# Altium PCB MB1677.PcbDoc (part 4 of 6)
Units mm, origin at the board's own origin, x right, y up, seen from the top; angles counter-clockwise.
Board outline 78 x 105 mm, 6 copper layers (Top Layer, Signal Layer 1, Signal Layer 2, Signal Layer 3, Signal Layer 4, Bottom Layer), stack 1.574 mm thick; 404 components, 325 nets, 1691 pads, 961 vias.
Unrouted connection lines stored in the file: 9.
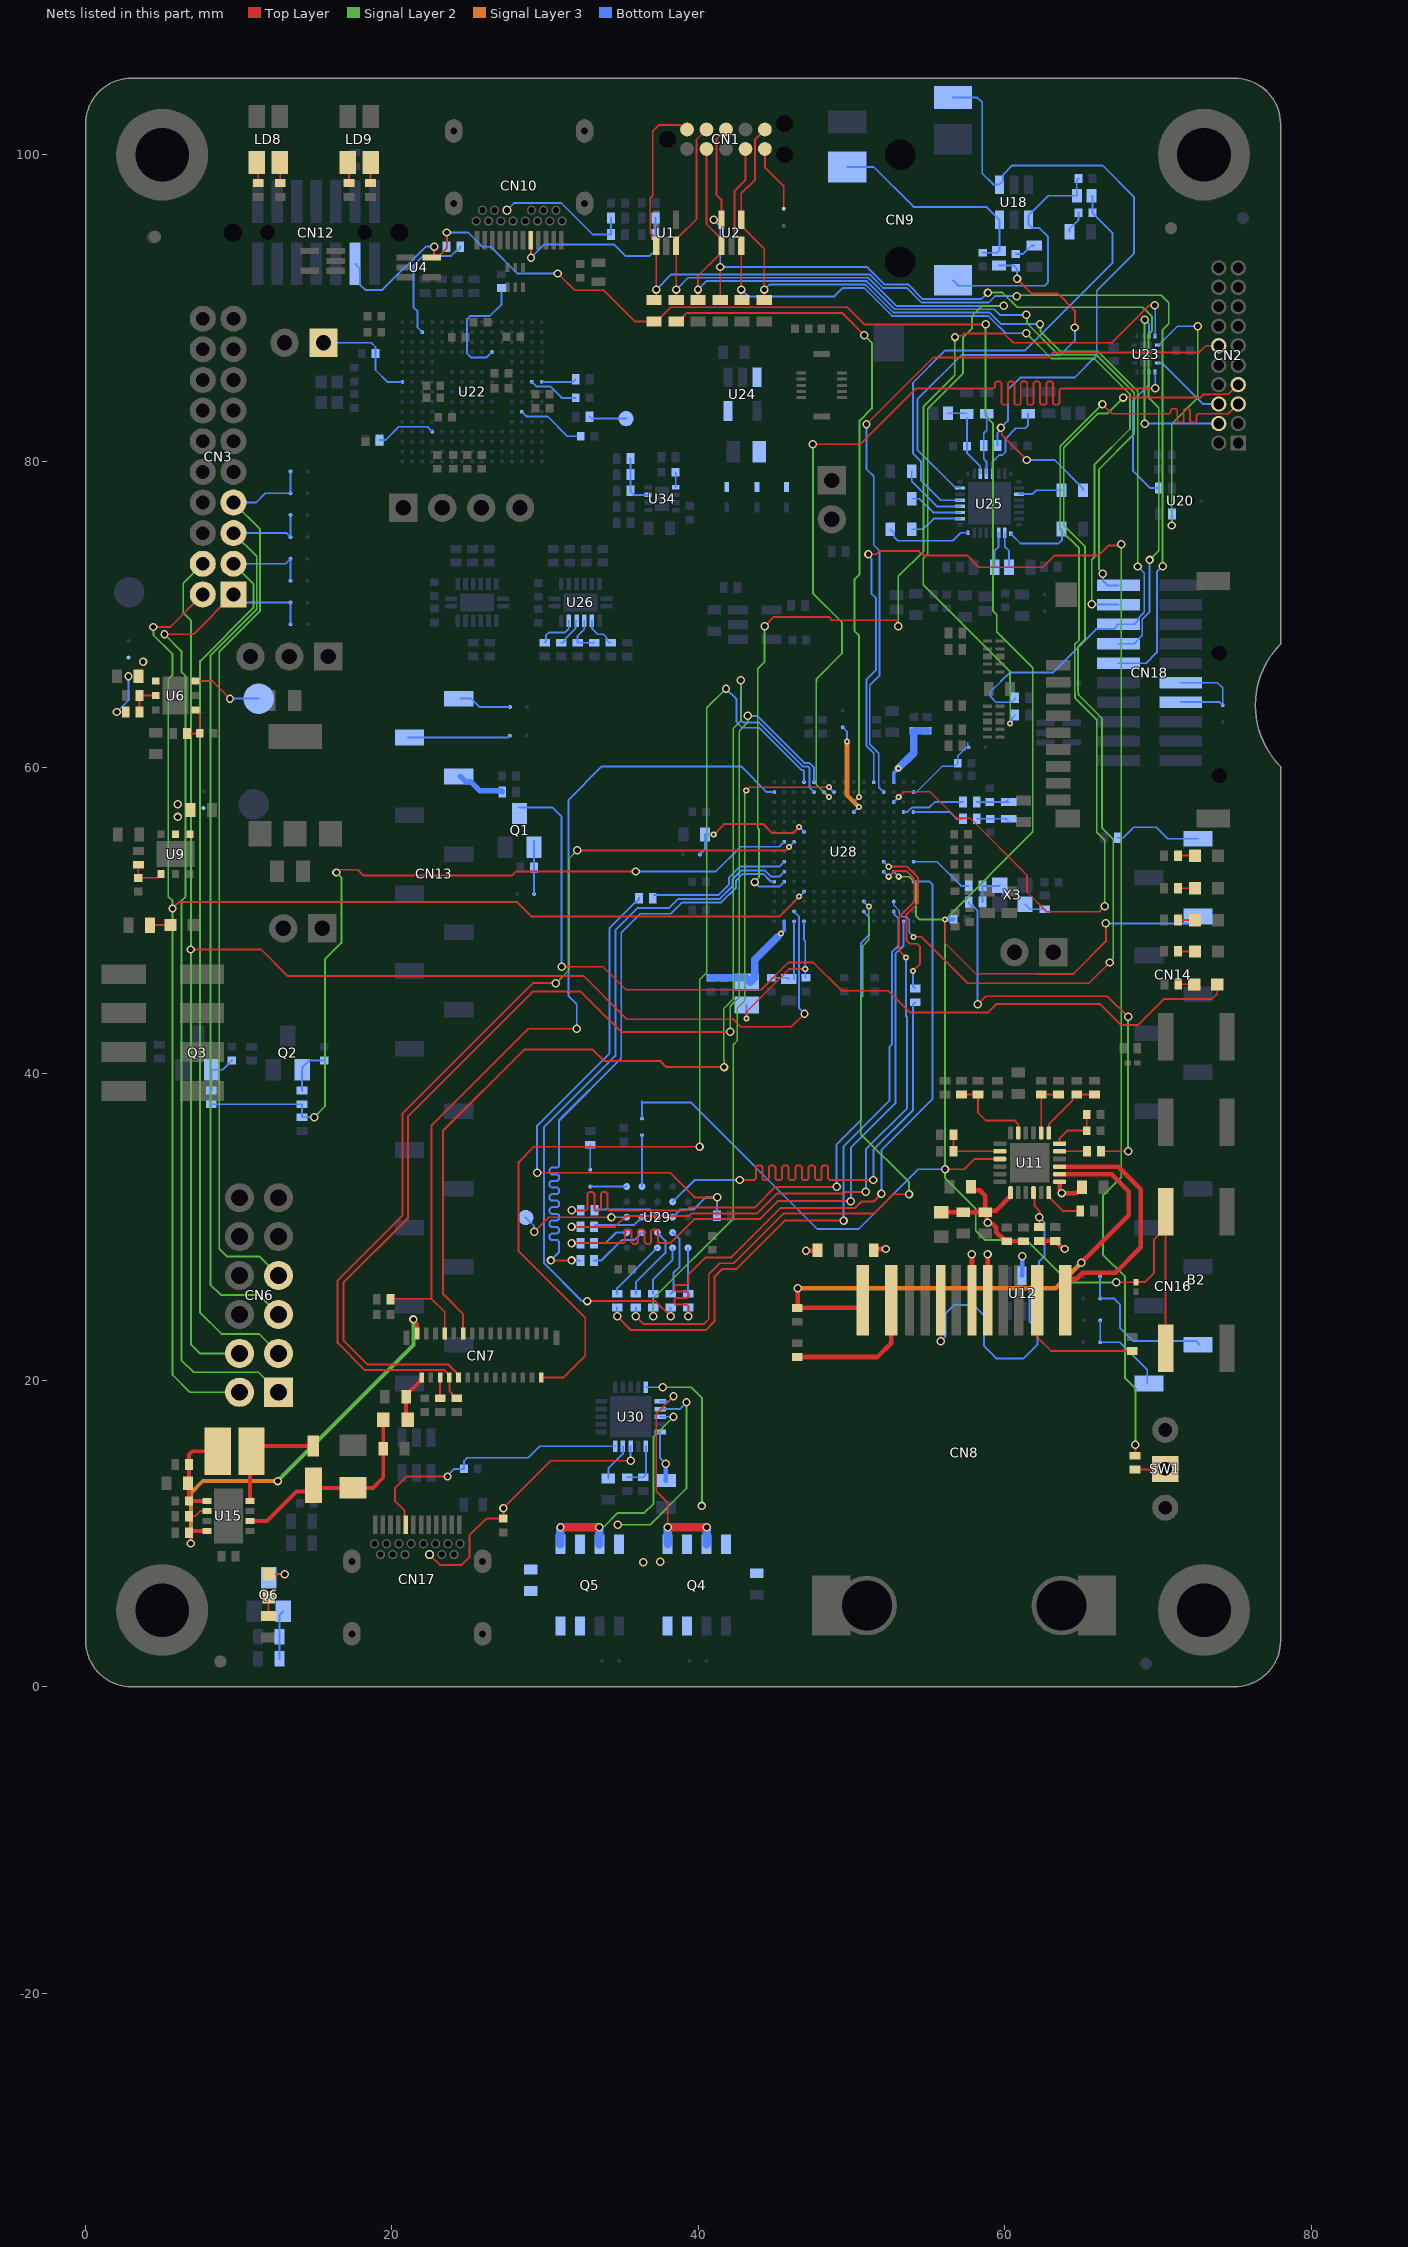
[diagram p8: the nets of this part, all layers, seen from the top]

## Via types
v1: diameter 0.55, hole 0.35, Top Layer to Bottom Layer, tented both sides, 748 vias
v2: diameter 0.4, hole 0.2, Top Layer to Bottom Layer, tented both sides, 203 vias
v3: diameter 0.6, hole 0.3, Top Layer to Bottom Layer, tented both sides, 9 vias
v4: diameter 0.55, hole 0.33, Top Layer to Bottom Layer, tented both sides, 1 vias

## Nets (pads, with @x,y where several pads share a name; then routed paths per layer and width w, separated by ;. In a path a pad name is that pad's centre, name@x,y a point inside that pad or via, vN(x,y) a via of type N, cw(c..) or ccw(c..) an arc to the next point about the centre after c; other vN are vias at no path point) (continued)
LCD_NE1_CS: CN7.22 R44.1 U28.G13 | length 63.8
  Top Layer w0.13: R44.1@24.225,18.825 24.13,18.825 23.94,19.015 23.94,19.11 23.74,19.31 CN7.22@23.74,20.175 23.74,20.35 23.617,20.474 23.425,20.665 18.235,20.665 16.45,22.45 16.45,26.525 20.68,30.755 20.68,37.41 29.025,45.755 29.195,45.925 v1(30.7,45.925) ; v1(32.1,54.6) 36.4,54.6 45.7,54.6 v2(45.925,54.825)
  Signal Layer 2 w0.1: v1(30.7,45.925) 31.525,46.75 31.525,54.025 v1(32.1,54.6)
  Bottom Layer w0.13: v2(45.925,54.825) U28.G13@46.25,55.15
LCD_NOE: CN7.19 U28.B11 | length 70.6
  Top Layer w0.13: CN7.19@24.64,23.05 24.64,24.328 23.33,25.638 23.33,36.294 28.621,41.585 30.148,41.585 33.103,41.585 33.843,40.845 37.504,40.845 37.899,40.45 v1(41.675,40.45)
  Signal Layer 2 w0.1: v1(41.675,40.45) 41.675,40.955 41.65,40.98 41.65,41.625 41.65,44.275 42.275,44.9 42.275,62.55 42.775,63.05 v1(42.775,65.7)
  Bottom Layer w0.13: v1(42.775,65.7) 42.775,63.075 42.925,62.925 43.959,62.925 46.747,60.137 46.814,60.07 47.139,60.07 47.25,59.959 47.25,58.7 U28.B11@47.55,58.4
LCD_NWE: CN7.20 U28.A11 | length 78.3
  Top Layer w0.13: CN7.20@24.34,20.175 24.255,20.26 24.255,20.445 23.655,21.045 18.392,21.045 16.83,22.607 16.83,26.367 21.06,30.597 21.06,37.253 29.182,45.375 32.325,45.375 33.562,44.137 34.955,42.745 36.4,42.745 42.07,42.745 v1(42.075,42.75)
  Signal Layer 2 w0.1: v1(42.075,42.75) 42.075,44.417 42.675,45.017 42.675,62.4 43.225,62.95 v1(43.225,63.375)
  Bottom Layer w0.13: v1(43.225,63.375) 43.834,63.375 46.909,60.3 47.25,60.3 47.55,60 U28.A11@47.55,59.05
LCD_PWR_ON: R101.1 R102.1 R103.2 U28.G14 | length 54.8
  Top Layer w0.12: v1(16.375,53.15) 16.55,53.325 17.775,53.325 18.15,52.95 27.825,52.95 28.09,53.215 v1(35.915,53.215)
  Signal Layer 2 w0.12: v1(14.925,37.175) 15.625,37.875 15.625,47.475 16.7,48.55 16.7,52.825 v1(16.375,53.15)
  Bottom Layer w0.12: R102.1@8.2,38.025 R101.1@14.125,38.025 R103.2@14.125,37.175 v1(14.925,37.175) ; v1@35.9,53.2 v1(35.915,53.215) 41.144,53.215 42.754,54.825 45.275,54.825 U28.G14@45.6,55.15
LCD_RST: CN7.23 R41.2 U28.B15 | length 58.8
  Top Layer w0.12: R41.2@19.953,25.325 22.575,25.325 ; CN7.23@23.44,23.05 23.44,24.46 22.575,25.325 ; v1(32.05,42.95) 28.9,42.95 22.575,36.625 22.575,25.325
  Bottom Layer w0.12: v1(32.05,42.95) 32.06,42.96 32.06,44.54 31.525,45.075 31.525,57.9 33.7,60.075 36.4,60.075 42.8,60.075 44.475,58.4 U28.B15@44.95,58.4
LCD_TE: CN7.2 U28.A12 | length 69.7
  Top Layer w0.12: CN7.2@29.74,20.175 31.191,20.175 32.62,21.605 32.62,24.08 28.265,28.435 28.265,34.25 29.265,35.25 v1(40.075,35.25)
  Signal Layer 2 w0.1: v1(40.075,35.25) 40.075,46.15 40.55,46.625 40.55,63.9 v1(41.8,65.15)
  Bottom Layer w0.12: v1(41.8,65.15) 42.49,64.46 42.49,62.96 42.848,62.602 43.964,62.602 46.721,59.845 46.83,59.845 46.9,59.775 U28.A12@46.9,59.05
LED_A: C49.2 CN7.28 L2.2 | length 3.3
  Top Layer w0.25: L2.2@21.025,17.425 20.925,17.525 20.925,19.05 21.85,19.975 21.915,19.975 21.94,20 CN7.28@21.94,20.175
LED_K: CN7.29 R52.2 U15.4 | length 26.5
  Top Layer w0.25: v1(6.875,9.35) 6.875,9.925 R52.2@6.75,10.05 6.875,10.175 U15.4@7.925,10.175 ; v1(21.4,23.975) 21.4,23.941 21.651,23.69 21.651,23.061 CN7.29@21.64,23.05
  Signal Layer 2 w0.25: v1@12.537,13.437 21.4,22.3 v1(21.4,23.975)
  Signal Layer 3 w0.25: v1(6.875,9.35) 6.875,12.657 7.643,13.425 v1(12.55,13.425)
MEMS_LED: CN2.12 U28.B4 | length 50.1
  Top Layer w0.12: v1(50.975,82.4) 55.339,86.764 62.814,86.764 63.15,87.1 72.7,87.1 73.135,87.535 CN2.12@73.965,87.535
  Bottom Layer w0.12: v1(50.975,82.4) 50.975,79.475 51.45,79 51.45,74.525 51.79,74.185 51.825,74.15 51.825,66.01 51.185,65.37 51.185,61.515 51.775,60.925 51.775,58.725 U28.B4@52.1,58.4
MICVDD: C69.2 C73.2 L5.2 U25.19 | length 5.2
  Bottom Layer w0.12: L5.2@56.3,83.125 C69.2@57.475,83.125 ; C69.2@57.525,82.825 C73.2@57.525,80.975 57.525,80.55 58.4,79.675 U25.19@58.4,79.175
NetC22_2: C22.2 R15.2 SB10.1 U6.4 | length 3.2
  Top Layer w0.12: v1(2.025,63.625) R15.2@2.625,63.625
  Bottom Layer w0.12: v1(2.025,63.625) 2.8,64.4 v1(2.8,65.95)
  other v1: 3.75,66.9
NetC26_2: C26.2 R17.2 U6.1 | length 2.5
  Top Layer w0.12: R17.2@6.625,62.225 C26.2@7.45,62.225 7.45,63.475 7.365,63.56 7.365,63.585 7.2,63.75 U6.1@7.175,63.75
NetC27_2: C27.2 SB13.1 U9.4 U9.5
  other v1: 6.025,56.775 6.025,57.6
NetC34_2: C34.2 R19.2 U9.1 | length 2.4
  Top Layer w0.1: R19.2@3.45,53.65 C34.2@3.45,52.8 4.675,52.8 4.725,52.85 4.75,52.85 4.925,53.025 U9.1@4.925,53.05
NetC38_2: C38.2 C39.2 U11.6 | length 3.4
  Top Layer w0.12: U11.6@63.575,35.45 63.575,35.8 64.075,36.3 C39.2@65.35,36.3 C38.2@65.35,37.35
NetC40_1: C40.1 C41.2 C42.2 C43.2 C45.2 C46.2 CN8.5 CN8.6 L1.1 R110.2 R111.2 R112.2 R113.2 U11.1 U11.19 U12.5 | length 24.6
  Top Layer w0.3: v1(47.025,28.45) 47.675,28.45 C45.2@47.775,28.35 ; C46.2@51.45,28.35 51.45,28.405 51.62,28.575 v1(52.225,28.575) ; L1.1@55.85,30.975 C42.2@57.3,30.975 C43.2@58.725,30.975 ; C40.1@57.8,32.625 57.8,32.569 57.97,32.399 58.376,32.399 58.725,32.05 C43.2@58.725,30.975 ; v1(57.855,28.225) 57.86,28.22 CN8.6@57.86,25.22 ; v1(58.875,28.225) 58.88,28.22 CN8.5@58.88,25.22 ; U11.19@60.375,32.25 60.375,31.975 60.325,31.975 59.426,31.076 58.826,31.076 C43.2@58.725,30.975 ; R112.2@61.225,29.075 R113.2@60.125,29.075 60.03,29.075 59.925,29.18 59.925,29.2 59.45,29.675 59.45,29.975 59.196,30.229 58.926,30.229 v1(58.878,30.276) 58.83,30.324 58.83,30.87 C43.2@58.725,30.975 ; R111.2@62.25,29.1 R110.2@63.3,29.1 63.395,29.1 63.5,28.995 63.5,28.9 63.777,28.623 63.877,28.623 v1(63.925,28.575) ; U11.1@63.575,32.95 63.575,32.375 v1(63.725,32.225) 64.675,32.225 64.755,32.305 64.88,32.305 65.05,32.475 C41.2@65.05,32.6
  Bottom Layer w0.3: U12.5@61.125,26.82 61.15,26.845 v1(61.15,28.1) v1@61.125,28.1
NetC51_2: C51.2 C52.2 D1.2 L2.1 U15.6 | length 13.8
  Top Layer w0.25: U15.6@10.725,10.825 11.85,10.825 13.761,12.736 14.486,12.736 14.875,13.125 15.025,12.975 C51.2@17.45,12.975 18.75,12.975 19.425,13.65 C52.2@19.425,15.525 L2.1@19.425,17.425
NetC53_2: C53.2 C54.1 L3.1 R49.2 U15.1 | length 6.2
  Top Layer w0.25: U15.1@7.925,12.125 C54.1@6.75,12.125 6.75,13.2 C53.2@6.675,13.275 6.75,13.35 R49.2@6.75,14.5 6.75,15.15 6.975,15.375 L3.1@8.625,15.375
NetC59_2: C59.2 U22.M10 | length 7.6
  Bottom Layer w0.12: U22.M10@26.525,87.125 26.175,86.775 25.15,86.775 24.9,87.025 24.9,89.275 25.1,89.475 26.375,89.475 27.15,90.25 C59.2@27.15,91.05
NetC68_2: C68.2 JP5.1 U22.J1 | length 7.1
  Bottom Layer w0.12: JP5.1@15.525,87.725 18.65,87.725 18.925,87.45 C68.2@18.925,87.025 18.925,85.95 19.7,85.175 U22.J1@20.675,85.175
NetC70_2: C70.2 U22.J14 | length 3.3
  Bottom Layer w0.12: U22.J14@29.125,85.175 29.425,84.875 30.325,84.875 31.075,84.125 C70.2@32,84.125
NetC76_1: C76.1 U25.8 | length 5.7
  Bottom Layer w0.12: C76.1@52.525,75.55 52.785,75.29 52.785,75.04 53.025,74.8 56.6,74.8 57.125,75.325 U25.8@57.6,75.325
NetC76_2: C76.2 U25.10 | length 3.4
  Bottom Layer w0.12: C76.2@53.925,75.55 54.65,75.55 55.35,76.25 U25.10@57.075,76.25
NetC77_2: C77.2 U22.F13 | length 4.3
  Bottom Layer w0.12: U22.F13@28.475,83.225 28.775,82.925 30.15,82.925 31.45,81.625 C77.2@32.075,81.625
NetC78_2: C78.2 U34.1 | length 1
  Bottom Layer w0.12: C78.2@38.5,79.275 38.525,79.25 U34.1@38.525,78.3
NetC79_1: C79.1 R76.1 U25.20 | length 4.1
  Bottom Layer w0.12: U25.20@58.8,79.175 58.8,79.975 58.625,80.15 R76.1@58.625,81.025 58.625,81.825 58.825,82.025 C79.1@58.825,83.1
NetC80_2: C80.2 D2.2 D3.2 D4.2 U24.3 U24.5
NetC81_2: C81.2 U25.11 | length 3.5
  Bottom Layer w0.12: C81.2@53.925,77.55 54.425,77.55 55.325,76.65 U25.11@57.075,76.65
NetC82_1: C82.1 U25.27 | length 2.9
  Bottom Layer w0.12: U25.27@60.925,77.85 61.8,77.85 62.05,78.1 C82.1@63.7,78.1
NetC82_2: C82.2 CN9.2 R76.2 U18.1 | length 47.8
  Top Layer w0.12: v1(59.75,82.175) 59.805,82.12 59.805,81.72 61.425,80.1 v1(61.425,80.075)
  Bottom Layer w0.12: CN9.2@56.625,103.75 56.641,103.734 58.205,103.734 58.525,103.414 58.525,98.775 59.24,98.06 59.64,98.06 U18.1@59.65,98.05 59.89,98.29 59.89,98.69 60.5,99.3 66.38,99.3 68.425,97.255 68.425,93.55 66,91.125 66,86.9 64.55,85.45 61,85.45 60.2,84.65 60.2,82.625 v1(59.75,82.175) 59.75,82.059 59.525,81.834 R76.2@59.525,81.025 ; v1(61.425,80.075) 63.25,80.075 65.1,78.225 C82.2@65.1,78.1
NetC83_2: C83.2 U25.12 | length 4.5
  Bottom Layer w0.12: C83.2@53.925,79.35 53.925,78.681 55.556,77.05 U25.12@57.075,77.05
NetC84_2: C84.2 U25.21 | length 5.4
  Bottom Layer w0.12: U25.21@59.2,79.175 59.2,79.95 59.65,80.4 59.85,80.4 60.05,80.6 60.05,81.475 60.725,82.15 61.325,82.15 61.525,82.35 C84.2@61.525,83.1
NetC86_1: C86.1 R77.2 | length 1.5
  Bottom Layer w0.12: R77.2@64.225,94.975 64.225,95.155 64.82,95.75 C86.1@64.82,96.225
NetC86_2: C86.2 L9.1 U25.13 | length 30.9
  Bottom Layer w0.12: U25.13@57.075,77.45 55.825,77.45 54.525,78.75 54.525,80 54,80.525 54,85.1 56.125,87.225 59.95,87.225 61.325,87.225 67.025,92.925 67.025,94.895 65.72,96.2 65.72,97.255 L9.1@65.65,97.325
NetC87_1: C87.1 R79.2 | length 1.4
  Bottom Layer w0.12: C87.1@60.725,93.525 61.195,93.525 61.745,94.075 R79.2@61.925,94.075
NetC87_2: C87.2 L10.1 U25.15 | length 27.5
  Top Layer w0.12: v1(60.8,91.9) 60.8,91.87 61.72,90.95 63.45,90.95 64.575,89.825 v1(64.575,88.725)
  Bottom Layer w0.12: U25.15@57.075,78.25 57.025,78.3 56.75,78.3 54.3,80.75 54.3,84.05 57.175,86.925 63.625,86.925 64.575,87.875 v1(64.575,88.725) ; L10.1@59.625,92.775 60.575,92.775 C87.2@60.725,92.625 60.8,92.55 v1(60.8,91.9)
NetC95_1: C95.1 C96.2 C115.2 C116.1 L4.1 U28.A3 U28.R14 | length 12.3
  Bottom Layer w0.25: 45.175,48.95 45.6,49.375 U28.R14@45.6,49.95 ; U28.A3@52.75,59.05 52.75,59.65 v2(53.05,59.95)
  Bottom Layer w0.5: C116.1@40.825,46.275 C115.2@41.7,46.275 43.1,46.275 43.375,46 43.675,46.3 43.675,47.45 45.175,48.95 ; v2(53.05,59.95) 54.05,60.95 C96.2@54.05,62.4 C95.1@54.925,62.4
  other v2: 45.388,49.163
NetC100_2: C100.2 SB12.2 U28.B1 | length 5.3
  Bottom Layer w0.1: U28.B1@54.05,58.4 54.057,58.407 54.232,58.407 55.9,60.075 56.725,60.075 C100.2@56.925,60.275 56.925,60.75 57.471,61.296 57.596,61.296 SB12.2@57.625,61.325 ; 57.575,61.61 57.575,61.461 57.596,61.44 SB12.2@57.596,61.337
NetC102_2: C102.2 R88.1 X2.2 | length 2.3
  Bottom Layer w0.1: R88.1@58.175,57.75 C102.2@59.025,57.75 X2.2@60.25,57.75 ; X2.2@60.1,57.8 X2.2@60.25,57.95
NetC104_2: C104.2 R89.1 X2.1 | length 2.3
  Bottom Layer w0.1: R89.1@58.175,56.65 C104.2@59.05,56.65 X2.1@60.15,56.65 ; X2.1@60,56.7 X2.1@60.25,56.45
NetC105_2: C105.2 SB14.2 U28.F12 | length 8.7
  Top Layer w0.13: v2(41,55.625) 41.675,56.3 44.25,56.3 44.825,55.725 46.175,55.725 v2(46.575,56.125)
  Bottom Layer w0.13: SB14.2@40.1,54.325 40.425,54.65 C105.2@40.425,55.625 v2(41,55.625) ; v2(46.575,56.125) U28.F12@46.9,55.8
NetC113_2: C113.2 L4.2 U28.R12 | length 10
  Top Layer w0.12: v2(43.15,43.625) 43.15,44.075 45.925,46.85 v2(46.975,46.85)
  Bottom Layer w0.12: v2(43.15,43.625) L4.2@43.15,44.5 ; U28.R12@46.9,49.95 46.9,48.725 46.975,48.65 v2(46.975,46.85) ; v2@46.925,46.825 46.975,46.775 46.975,46.325 C113.2@47.025,46.275
NetC114_2: C114.2 R96.1 U28.R13 | length 4.9
  Bottom Layer w0.12: C114.2@44.75,46.275 45.825,46.275 R96.1@45.9,46.2 ; U28.R13@46.25,49.95 46.25,46.225 R96.1@46.275,46.2
NetC117_1: C117.1 Q2.1 R101.2 | length 3.1
  Bottom Layer w0.12: R101.2@14.125,38.925 14.125,40.25 Q2.1@14.15,40.275 14.15,40.435 14.59,40.875 C117.1@15.575,40.875
NetC118_1: C118.1 Q3.1 R102.2 | length 2.9
  Bottom Layer w0.12: R102.2@8.2,38.925 8.225,38.95 Q3.1@8.225,40.275 8.95,40.275 9.33,40.655 9.33,40.68 9.525,40.875 C118.1@9.55,40.875
NetC120_2: C120.2 CN17.A5 U30.15 | length 18.5
  Top Layer w0.12: CN17.A5@20.9,10.585 20.825,10.66 20.825,11.475 20.2,12.1 20.2,12.975 20.95,13.725 v1(23.625,13.725)
  Bottom Layer w0.12: v1(23.625,13.725) 23.625,13.775 24.07,14.22 C120.2@24.7,14.22 24.7,14.725 24.925,14.95 28.9,14.95 29.65,15.7 U30.15@34.575,15.7
NetC121_1: C121.1 U30.14 | length 2.5
  Bottom Layer w0.12: C121.1@34.125,13.6 34.125,14.25 35.075,15.2 U30.14@35.075,15.7
NetC123_2: C123.2 CN17.B5 U30.13 | length 18.4
  Top Layer w0.12: CN17.B5@22.45,8.625 23.125,7.95 24.55,7.95 25.05,8.45 25.05,9.875 26.15,10.975 26.77,10.975 C123.2@27.255,10.975 ; C123.2@27.275,10.975 C123.2@27.255,10.975 ; v1(35.575,14.75) 30.375,14.75 v1(27.275,11.65) 27.275,10.995 C123.2@27.255,10.975
  Bottom Layer w0.12: v1(35.575,14.75) U30.13@35.575,15.7
NetC124_1: C124.1 Q5.2 Q5.4 U30.7 | length 13
  Signal Layer 2 w0.12: v1(34.725,10.575) 36.85,10.575 39.225,12.95 v1(39.225,18.575)
  Bottom Layer w0.12: U30.7@37.5,18.125 38.775,18.125 v1(39.225,18.575)
NetC124_2: C124.2 Q4.7 Q4.8 Q5.7 Q5.8 R121.2 U30.10 | length 3.3
  Bottom Layer w0.12: U30.10@37.5,16.625 37.5,14.925 v1(37.875,14.55)
  Bottom Layer w0.3: R121.2@37.875,13.45 v1(37.875,14.55)
  other v1: 36.4,8.125 37.5,8.15
NetC125_1: C125.1 Q4.2 Q4.4 U30.5 | length 11
  Signal Layer 2 w0.12: v1(37.675,19.55) 39.525,19.55 40.225,18.85 v1(40.225,11.8)
  Bottom Layer w0.12: U30.5@36.575,19.55 v1(37.675,19.55)
NetC128_2: C128.2 CN9.6 L9.2 U18.4 | length 16.5
  Bottom Layer w0.12: CN9.6@56.625,91.8 56.975,91.45 62.6,91.45 62.825,91.675 62.825,94.65 62.265,95.21 61.79,95.21 61.55,95.45 61.55,96.05 62.825,97.325 L9.2@64.7,97.325 64.7,98.33 C128.2@64.82,98.45
NetC129_2: C129.2 CN9.4 L10.2 U18.6 | length 14.5
  Bottom Layer w0.12: CN9.4@49.725,99.2 51.45,99.2 54.05,96.6 58.8,96.6 U18.6@59.65,95.75 59.65,93.75 L10.2@59.625,93.725 59.505,93.605 C129.2@58.55,93.605
NetCN1_2: CN1.2 CN18.2 R6.1 U2.1 | length 57.4
  Top Layer w0.12: R6.1@39.975,90.525 39.975,92.1 41.36,93.485 41.36,93.91 U2.1@41.5,94.05 41.36,94.19 41.36,94.64 40.53,95.47 CN1.2@40.53,100.38
  Signal Layer 2 w0.12: v1@61.425,89.575 v1(61.4,89.55) 61.45,89.5 61.45,89 63.5,86.95 65.975,86.95 68.45,84.475 68.45,81.775 66.15,79.475 66.15,72.935 66.4,72.685 v1(66.4,72.65)
  Bottom Layer w0.12: v1(39.975,91.2) 40.526,91.751 50.991,91.751 52.828,89.914 59.311,89.914 59.675,89.55 v1(61.4,89.55) ; v1(66.4,72.65) 66.4,72.2 66.71,71.89 CN18.2@67.415,71.89
NetCN1_4: CN1.4 CN18.4 R8.1 U2.3 | length 55.6
  Top Layer w0.12: R8.1@42.85,90.525 42.8,90.575 v1(42.8,91.2) U2.3@42.8,94.05 42.8,94.45 42.66,94.59 42.636,94.59 42.35,94.876 42.35,97.625 43.07,98.345 CN1.4@43.07,100.38
  Signal Layer 2 w0.12: v1(61.4,88.35) 63.05,86.7 65.85,86.7 68.175,84.375 68.175,82.1 65.85,79.775 65.85,73.74 65.675,73.565 v1(65.675,70.65)
  Bottom Layer w0.12: v1(42.8,91.2) 43.25,90.75 48.875,90.75 49.436,91.311 50.809,91.311 52.646,89.474 58.926,89.474 60.05,88.35 v1(61.4,88.35) ; v1(65.675,70.65) 67.385,70.65 CN18.4@67.415,70.62
NetCN1_5: CN1.5 SB17.2 | length 4.4
  Top Layer w0.12: CN1.5@44.34,100.38 44.34,99.185 45.575,97.95 SB17.2@45.575,96.475
NetCN1_6: CN1.6 CN18.6 R9.1 R97.2 U2.4 | length 69.2
  Top Layer w0.12: R9.1@44.3,90.525 44.3,93.875 42.965,95.21 42.94,95.21 42.8,95.35 U2.4@42.8,95.75 42.8,97.475 43.7,98.375 43.7,101.01 CN1.6@44.34,101.65
  Signal Layer 2 w0.12: v1(62.3,88.925) 62.339,88.886 62.339,88.461 63.625,87.175 66.075,87.175 68.675,84.575 v1(68.675,73.125)
  Bottom Layer w0.1: 59.75,65.625 59.05,64.925 59.05,64.65 59.45,64.25 60.47,64.25 60.675,64.455 R97.2@60.675,64.55
  Bottom Layer w0.12: v1(44.3,91.2) 44.631,91.531 50.9,91.531 52.737,89.694 59.018,89.694 59.761,88.95 62.275,88.95 v1(62.3,88.925) ; 59.75,65.625 60.325,66.2 63.125,66.2 65.965,69.04 67.105,69.04 CN18.6@67.415,69.35 68.44,69.35 68.75,69.66 68.75,69.79 69.1,70.14 69.1,72.7 v1(68.675,73.125)
NetCN1_8: CN1.8 CN18.8 R7.1 U2.5 | length 65.5
  Top Layer w0.12: v1(41,95.75) U2.5@41.5,95.75 41.5,97.075 41.175,97.4 41.175,101.025 CN1.8@41.8,101.65 ; R7.1@41.425,90.525 v1(41.425,92.675)
  Signal Layer 2 w0.12: v1(58.9,91) 59.85,91 60.8,90.05 69,90.05 69.6,89.45 69.6,88.475 69.39,88.265 69.39,84.93 69.39,84.135 70.05,83.475 70.05,74.15 v1(69.45,73.55)
  Bottom Layer w0.12: v1(41,95.75) 41.425,95.325 v1(41.425,92.675) 51,92.675 52.143,91.532 53.696,91.532 54.655,90.574 57.549,90.574 57.55,90.575 58.475,90.575 v1(58.9,91) ; CN18.8@67.415,68.08 68.44,68.08 68.75,68.39 68.75,68.4 68.975,68.625 68.975,69.683 69.45,70.158 v1(69.45,73.55)
NetCN1_9: CN1.9 R5.1 R98.2 U1.3 | length 67.7
  Top Layer w0.12: R5.1@38.55,90.525 U1.3@38.55,94.05 38.69,94.19 38.69,94.615 39.875,95.8 39.875,100.995 CN1.9@40.53,101.65
  Signal Layer 2 w0.1: v2(60.35,62.875) 60.35,65.625
  Signal Layer 2 w0.12: v1(59.932,90.134) 59.923,90.125 58.5,90.125 57.85,89.475 57.85,88.65 57.266,88.066 57.266,85.716 54.975,83.425 54.975,73.95 54.675,73.65 54.675,71.94 60.35,66.265 60.35,65.625
  Bottom Layer w0.1: v2(60.35,62.875) 60.47,62.995 60.47,63.22 R98.2@60.675,63.425
  Bottom Layer w0.12: v1(38.55,91.2) 39.321,91.971 51.082,91.971 52.919,90.134 v1(59.932,90.134) v1@59.932,90.135
NetCN1_10: CN1.10 CN18.10 R4.1 U1.1 | length 74.8
  Top Layer w0.12: R4.1@37.1,90.525 37.25,90.675 v1(37.25,91.2) U1.1@37.25,94.05 37.11,94.19 37.11,94.64 36.855,94.895 36.855,97.155 37.025,97.325 37.025,101.525 37.45,101.95 38.8,101.95 39.1,101.65 CN1.10@39.26,101.65
  Signal Layer 2 w0.12: v1(60.775,90.775) 60.825,90.825 70.2,90.825 70.697,90.328 70.697,88.972 70.3,88.575 v1(70.3,73.15)
  Bottom Layer w0.12: v1(37.25,91.2) 38.241,92.191 51.173,92.191 52.051,91.312 53.605,91.312 54.564,90.354 58.938,90.354 59.36,90.775 v1(60.775,90.775) ; CN18.10@67.415,66.81 69.22,66.81 69.925,67.515 69.925,72.775 v1(70.3,73.15)
NetCN7_24: CN7.24 R43.1 | length 1.4
  Top Layer w0.12: CN7.24@23.14,20.175 23.14,18.835 R43.1@23.15,18.825
NetCN8_1: CN8.1 U11.3 | length 16.7
  Top Layer w0.3: U11.3@63.575,33.95 67.4,33.95 68.875,32.475 68.875,28.675 67.225,27.025 65.075,27.025 64.689,26.639 64.305,26.639 63.96,26.294 CN8.1@63.96,25.22
NetCN8_2: CN8.2 R50.2 | length 9
  Top Layer w0.12: CN8.2@62.12,25.22 62.132,25.208 62.132,22.81 63.018,21.925 R50.2@68.325,21.925
NetCN8_11: CN8.11 R54.2 | length 9.3
  Top Layer w0.3: R54.2@46.47,21.505 R54.2@46.45,21.525 51.675,21.525 52.58,22.43 CN8.11@52.58,25.22
NetCN8_12: CN8.12 R53.2 U11.2 | length 36.1
  Top Layer w0.3: v1(46.475,26) 46.475,24.75 R53.2@46.45,24.725 50.485,24.725 50.74,24.98 CN8.12@50.74,25.22 ; U11.2@63.575,33.45 66.975,33.45 68.1,32.325 68.1,30.775 v1(64.995,27.67)
  Signal Layer 3 w0.3: v1(46.475,26) 63.325,26 v1(64.995,27.67)
NetCN10_A5: CN10.A5 R45.1 R46.1 | length 12.2
  Top Layer w0.12: CN10.A5@29.05,94.42 29.075,94.395 v1(29.075,93.275)
  Bottom Layer w0.12: v1(29.075,93.275) 29.95,94.15 34.475,94.15 35.225,93.4 36.825,93.4 37.2,93.775 R45.1@37.2,94.8 R46.1@37.2,95.875
NetCN10_B5: CN10.B5 R47.1 R48.1 | length 8.9
  Bottom Layer w0.12: CN10.B5@27.5,96.38 27.971,96.851 31.036,96.851 33.087,94.8 R48.1@34.3,94.8 R47.1@34.3,95.875
NetCN13_8: CN13.8 R95.1 | length 3.2
  Bottom Layer w0.35: CN13.8@24.466,59.419 24.801,59.084 25.133,59.084 25.724,58.492 27.12,58.492 27.2,58.412 R95.1@27.2,58.4
NetCN13_9: CN13.9 SB16.1 | length 6.7
  Bottom Layer w0.12: CN13.9@21.038,61.959 27.563,61.959 27.679,62.075 SB16.1@27.7,62.075
NetCN13_10: CN13.10 SB19.1 | length 3.5
  Bottom Layer w0.12: CN13.10@24.466,64.499 25.165,64.499 25.714,63.95 SB19.1@27.7,63.95
NetCN14_8: CN14.8 R90.1 | length 5.8
  Bottom Layer w0.12: R90.1@67.375,55.41 67.38,55.415 67.74,55.415 68.425,56.1 69.9,56.1 70.645,55.355 CN14.8@72.615,55.355
NetCN16_1: CN16.1 SB21.2 SB23.2 | length 6.1
  Bottom Layer w0.12: SB23.2@66.227,23.915 SB21.2@66.227,22.49 67.51,22.49 69.298,20.702 CN16.1@69.298,19.795
NetCN16_2: CN16.2 SB24.2 SB25.2 | length 10.1
  Bottom Layer w0.12: SB25.2@66.225,26.775 SB24.2@66.225,25.35 67.1,25.35 67.525,24.925 67.525,23.4 68.35,22.575 72.487,22.575 CN16.2@72.727,22.335
NetCN18_11: CN18.11 CN18.13 SB18.2 | length 6.8
  Bottom Layer w0.12: CN18.13@71.485,64.27 74.03,64.27 SB18.2@74.225,64.075 74.225,65.2 73.885,65.54 CN18.11@71.485,65.54
NetD1_1: D1.1 L3.2 U15.8 | length 7.5
  Top Layer w0.25: U15.8@10.725,12.125 10.725,15.275 L3.2@10.825,15.375 11.17,15.72 D1.1@14.875,15.72
NetLD1_2: LD1.2 R26.2 | length 1.1
  Top Layer w0.12: R26.2@71.3,48 72.405,48 LD1.2@72.415,47.99
NetLD2_2: LD2.2 R25.2 | length 1.1
  Top Layer w0.12: R25.2@71.3,50.05 72.405,50.05 LD2.2@72.415,50.04
NetLD3_2: LD3.2 R24.2 | length 1.1
  Top Layer w0.12: R24.2@71.3,52.125 72.405,52.125 LD3.2@72.415,52.115
NetLD4_2: LD4.2 R22.2 | length 1.1
  Top Layer w0.12: R22.2@71.3,54.25 72.405,54.25 LD4.2@72.415,54.24
NetLD5_1: LD5.1 R23.2 | length 1.3
  Top Layer w0.12: R23.2@4.21,49.713 4.223,49.725 LD5.1@5.547,49.725
NetLD6_1: LD6.1 R27.1 | length 1
  Top Layer w0.12: R27.1@71.328,45.85 72.355,45.85 LD6.1@72.365,45.84
NetLD6_2: LD6.2 Q1.3 | length 60.6
  Top Layer w0.12: v1(31.075,47) 33.775,47 35.275,45.5 44.1,45.5 45.875,47.275 47.5,47.275 49.35,45.425 52.4,45.425 53.825,44 58.9,44 59.475,44.575 66.2,44.575 67.575,43.2 68.7,43.2 70.4,44.9 73.525,44.9 73.865,45.24 LD6.2@73.865,45.84
  Bottom Layer w0.12: Q1.3@28.325,57.4 30.475,57.4 31.075,56.8 v1(31.075,47)
NetLD7_1: LD7.1 R56.1 | length 1.2
  Top Layer w0.12: R56.1@11.95,4.62 LD7.1@11.95,5.845
NetLD7_2: LD7.2 Q6.3 | length 2.2
  Top Layer w0.12: LD7.2@11.95,7.345 12.995,7.345 v1(13,7.35)
  Bottom Layer w0.12: Q6.3@11.95,7.12 12.18,7.35 v1(13,7.35)
NetLD8_1: LD8.1 R130.1 | length 1.4
  Top Layer w0.12: R130.1@12.709,98.15 12.709,99.474 LD8.1@12.735,99.5
NetLD8_2: LD8.2 R131.1 | length 1.4
  Top Layer w0.12: LD8.2@11.235,99.5 11.275,99.46 R131.1@11.275,98.15
NetLD9_1: LD9.1 R59.1 | length 1.4
  Top Layer w0.12: R59.1@18.6,98.15 18.6,99.49 LD9.1@18.61,99.5
NetLD9_2: LD9.2 R60.2 | length 1.4
  Top Layer w0.12: LD9.2@17.11,99.5 17.199,99.411 R60.2@17.199,98.15
NetQ1_1: Q1.1 R91.2 SB15.2 | length 3.5
  Bottom Layer w0.12: SB15.2@29.275,51.75 R91.2@29.275,53.45 Q1.1@29.275,55.2
NetQ4_1: Q4.1 Q4.3 U30.6 | length 15.1
  Top Layer w0.12: v1(38,10.4) 38,12 37.25,12.75 37.25,17.825 v1(38.375,18.95)
  Top Layer w0.55: v1(38,10.4) v1(40.54,10.4)
  Bottom Layer w0.12: U30.6@37.5,18.625 38.05,18.625 v1(38.375,18.95)
  Bottom Layer w0.3: v1@37.995,10.395 v1(38,10.4) ; v1@40.535,10.395 v1(40.54,10.4)
  Bottom Layer w0.55: Q4.1@37.995,9.305 v1@37.995,10.395 ; Q4.3@40.535,9.305 v1@40.535,10.395
NetQ5_1: Q5.1 Q5.3 U30.8 | length 16
  Top Layer w0.55: v1(31,10.4) v1(33.54,10.4)
  Signal Layer 2 w0.12: v1(33.54,10.4) 33.612,10.472 33.872,10.472 34.75,11.35 36.475,11.35 37.075,11.95 37.075,16.325 v1(38.375,17.625)
  Bottom Layer w0.12: U30.8@37.5,17.625 v1(38.375,17.625)
  Bottom Layer w0.3: v1@30.995,10.395 v1(31,10.4) ; v1@33.535,10.395 v1(33.54,10.4)
  Bottom Layer w0.55: Q5.1@30.995,9.305 v1@30.995,10.395 ; Q5.3@33.535,9.305 v1@33.535,10.395
NetQ6_1: Q6.1 R126.1 R127.2 | length 3.2
  Bottom Layer w0.12: R127.2@12.65,1.82 R126.1@12.65,3.27 12.65,4.67 Q6.1@12.9,4.92
NetR14_2: R14.2 R15.1 U6.5 | length 2.1
  Top Layer w0.12: R15.1@3.525,63.625 R14.2@3.525,64.7 U6.5@4.575,64.7
NetR28_2: R28.2 R35.1 U11.11 | length 5.8
  Top Layer w0.12: R35.1@57.175,38.65 R28.2@58.25,38.65 58.25,37.475 58.775,36.95 60.65,36.95 60.875,36.725 U11.11@60.875,36.15
NetR30_1: R30.1 R31.2 U11.8 | length 3.6
  Top Layer w0.12: U11.8@62.375,36.15 R30.1@62.375,38.65 R31.2@63.5,38.65
NetR32_1: R32.1 R33.2 U11.7 | length 4.4
  Top Layer w0.12: U11.7@62.875,36.15 62.875,36.725 64.44,38.29 64.44,38.455 64.635,38.65 R32.1@64.7,38.65 R33.2@65.85,38.65
NetR37_2: R37.2 R39.1 U11.14 | length 4.1
  Top Layer w0.12: R37.2@56.65,36.025 R39.1@56.65,34.95 U11.14@59.675,34.95
NetR38_1: R38.1 U11.5 | length 1.8
  Top Layer w0.12: U11.5@63.575,34.95 R38.1@65.375,34.95
NetR40_1: R40.1 U11.24 | length 2.7
  Top Layer w0.12: U11.24@62.875,32.25 62.875,31.983 62.964,31.894 62.981,31.894 63.825,31.05 R40.1@64.925,31.05
NetR42_1: R42.1 U28.A5 | length 94.1
  Top Layer w0.12: v1(51.1,73.925) 51.6,73.925 51.805,74.13 54.395,74.13 54.675,73.85 57.537,73.85 58.312,73.075 62.488,73.075 63.262,73.85 66.125,73.85 66.775,74.5 67.525,74.5 v1(67.6,74.575) ; R42.1@68.5,15.075 68.525,15.1 v1(68.525,15.8)
  Signal Layer 2 w0.12: v1(67.6,74.575) 67.6,33.25 66.4,32.05 66.4,28.2 67.85,26.75 67.85,20.15 68.525,19.475 v1(68.525,15.8)
  Bottom Layer w0.12: v1(51.1,73.925) 51.1,73.84 51.3,73.64 51.3,71.336 51.6,71.036 51.6,66.375 50.965,65.74 50.965,61.424 51.45,60.939 U28.A5@51.45,59.05
NetR42_2: R42.2 SW1.1 | length 2
  Top Layer w0.12: R42.2@68.5,14.175 70.425,14.175 SW1.1@70.475,14.225
NetR51_2: R51.2 U15.2 | length 1.3
  Top Layer w0.12: R51.2@6.75,11.125 7.15,11.125 7.5,11.475 U15.2@7.925,11.475
NetR57_2: R57.2 U25.1 | length 4.5
  Bottom Layer w0.12: U25.1@60.425,75.225 U25.1@60.4,75.25 60.4,75.21 60.45,75.16 60.49,75.16 61.025,74.625 63.525,74.625 63.725,74.825 R57.2@63.725,75.575
NetR61_1: R61.1 U26.14 | length 2.7
  Bottom Layer w0.12: R61.1@29.975,68.15 30.05,68.225 30.05,68.625 30.25,68.825 31.3,68.825 31.54,69.065 31.54,69.565 U26.14@31.55,69.575
NetR62_1: R62.1 U25.2 | length 2.4
  Bottom Layer w0.12: U25.2@60,75.325 60,74.425 60.275,74.15 R62.1@60.275,73.075
NetR63_1: R63.1 R72.1 U26.12 | length 2.7
  Bottom Layer w0.12: U26.12@32.55,69.575 32.55,69.04 32.115,68.605 32.115,68.16 R63.1@32.125,68.15 R72.1@33.2,68.15
NetR68_1: R68.1 U22.P3 | length 8.2
  Bottom Layer w0.12: U22.P3@21.975,88.425 21.675,88.725 21.675,89.775 21.4,90.05 21.4,92.75 22.05,93.4 23.85,93.4 24.16,93.71 24.255,93.71 24.45,93.905 R68.1@24.45,94
NetR69_1: R69.1 U26.13 | length 1.9
  Bottom Layer w0.12: R69.1@31.05,68.15 31.145,68.15 31.34,68.345 31.34,68.44 31.98,69.08 31.98,69.505 U26.13@32.05,69.575
NetR71_1: R71.1 U22.J15 | length 2.3
  Bottom Layer w0.12: U22.J15@29.775,85.175 31.825,85.175 R71.1@32,85.35
NetR73_1: R73.1 U25.3 | length 2.4
  Bottom Layer w0.12: R73.1@59.35,73.075 59.35,74.15 59.6,74.4 U25.3@59.6,75.325
NetR75_2: R75.2 TP13.1 | length 2.4
  Bottom Layer w0.12: R75.2@32.9,82.9 33.025,82.775 TP13.1@35.28,82.775
NetR78_1: R78.1 U26.11 | length 2.2
  Bottom Layer w0.12: U26.11@33.05,69.575 33.06,69.565 33.06,69.065 33.425,68.7 33.8,68.7 34.003,68.497 34.003,68.345 34.198,68.15 R78.1@34.275,68.15
NetR85_1: R85.1 U22.D4 | length 3.9
  Bottom Layer w0.12: R85.1@19.175,81.375 19.575,81.375 20.45,82.25 22.3,82.25 U22.D4@22.625,81.925
NetR86_1: R86.1 R128.1 R129.1 U34.7 | length 3.4
  Bottom Layer w0.12: R129.1@35.575,80.175 R86.1@35.575,79.125 R128.1@35.575,78.075 35.575,77.995 35.77,77.8 U34.7@36.725,77.8
NetR92_1: R92.1 R94.2 X3.3 | length 2.2
  Bottom Layer w0.12: R94.2@58.55,51.225 R92.1@58.55,52.275 59.625,52.275 X3.3@59.675,52.325
NetR92_2: R92.2 U28.J1 | length 4.3
  Bottom Layer w0.12: U28.J1@54.05,53.85 55.575,53.85 57.15,52.275 R92.2@57.65,52.275
NetR93_2: R93.2 X3.1 | length 1.4
  Bottom Layer w0.1: X3.1@61.325,51.075 61.65,50.75 62.125,50.75
  Bottom Layer w0.12: 62.125,50.75 R93.2@62.6,50.75
NetR104_1: R104.1 SB22.2 | length 1.6
  Bottom Layer w0.12: SB22.2@32.945,33.75 R104.1@32.945,35.375
NetR105_2: R105.2 U28.J4 | length 11.1
  Top Layer w0.12: 54.175,51 53.575,50.4 53.575,48.725 53.8,48.5 54.287,48.5 54.475,48.312
  Top Layer w0.13: v2(52.425,53.525) 53.625,53.525 54.32,52.83 54.32,51.145 54.175,51 ; v2(54,46.725) 54.475,47.2 54.475,48.312
  Bottom Layer w0.13: U28.J4@52.1,53.85 v2(52.425,53.525) ; v2(54,46.725) 54,45.725 R105.2@54.15,45.575
NetR106_1: R106.1 U28.J14 | length 9.7
  Bottom Layer w0.13: R106.1@37.1,51.665 41.303,51.665 41.995,52.357 41.995,52.814 42.706,53.525 45.275,53.525 U28.J14@45.6,53.85
NetR107_2: R107.2 U28.P6 | length 41.8
  Top Layer w0.13: v1(31.745,31.1) 32.67,31.1 32.778,31.207 32.778,32.181 32.885,32.289 33.1,32.289 33.208,32.181 33.208,31.185 33.315,31.077 33.53,31.077 33.638,31.185 33.638,32.181 33.745,32.289 33.96,32.289 34.068,32.181 34.068,31.207 34.175,31.1 34.741,31.1 39.228,31.1 39.408,31.28 43.68,31.28 45.025,32.625 v1(49.025,32.625)
  Bottom Layer w0.13: v1(31.745,31.1) R107.2@32.32,31.1 ; v1(49.025,32.625) 49.025,35.4 50.63,37.005 50.63,41.625 50.63,48.555 51.125,49.05 51.125,50.275 U28.P6@50.8,50.6
NetR109_1: R109.1 U28.K4 | length 45.4
  Top Layer w0.13: v1(31.72,30.025) 34.55,30.025 35.245,30.72 39.385,30.72 39.565,30.9 43.837,30.9 45.122,32.185 49.51,32.185 49.625,32.3 v1(50.925,32.3) ; v2(52.425,52.875) 52.8,53.25 53.575,53.25 54.09,52.735 54.09,51.24 53.1,50.25 53.1,48.05 v2(53.55,47.6)
  Bottom Layer w0.13: v1(31.72,30.025) R109.1@32.295,30.025 ; v1(50.925,32.3) 50.925,35.075 53.62,37.77 53.62,41.625 53.62,43.705 53.55,43.775 v2(53.55,47.6) ; U28.K4@52.1,53.2 v2(52.425,52.875)
NetR114_1: R114.1 U28.R2 | length 44.5
  Top Layer w0.13: v1(31.72,28.95) 35.027,28.95 35.092,28.95 35.199,29.057 35.199,29.752 35.307,29.859 35.522,29.859 35.629,29.752 35.629,29.019 35.737,28.911 35.952,28.911 36.059,29.019 36.059,29.752 36.167,29.859 36.382,29.859 36.489,29.752 36.489,29.019 36.597,28.911 36.812,28.911 36.919,29.019 36.919,29.752 37.027,29.859 37.242,29.859 37.349,29.752 37.349,29.057 37.457,28.95 37.775,28.95 38.152,28.95 39.722,30.52 43.995,30.52 45.175,31.7 v1(49.95,31.7)
  Bottom Layer w0.13: v1(31.72,28.95) R114.1@32.295,28.95 ; v1(49.95,31.7) 49.95,35.175 52.86,38.085 52.86,41.625 52.86,47.844 53.4,48.384 U28.R2@53.4,49.95
NetR115_1: R115.1 U28.L15 | length 43
  Top Layer w0.13: v1(30.375,27.825) v1(31.72,27.825)
  Bottom Layer w0.13: v1(30.375,27.825) 30.9,28.35 30.9,28.978 30.9,29.043 30.793,29.15 30.402,29.15 30.295,29.258 30.295,29.473 30.402,29.58 30.793,29.58 30.9,29.688 30.9,29.903 30.793,30.01 30.402,30.01 30.295,30.118 30.295,30.333 30.402,30.44 30.793,30.44 30.9,30.548 30.9,30.763 30.793,30.87 30.402,30.87 30.295,30.978 30.295,31.193 30.402,31.3 30.793,31.3 30.9,31.408 30.9,31.623 30.793,31.73 30.402,31.73 30.295,31.838 30.295,32.053 30.402,32.16 30.793,32.16 30.9,32.268 30.9,32.483 30.793,32.59 30.402,32.59 30.295,32.698 30.295,32.913 30.402,33.02 30.793,33.02 30.9,33.128 30.9,33.343 30.793,33.45 30.402,33.45 30.295,33.558 30.295,33.773 30.402,33.88 30.793,33.88 30.9,33.988 30.9,34.317 30.9,36.962 34.965,41.027 34.965,49.227 36.194,50.456 36.4,50.456 38.206,50.456 38.955,51.205 41.494,51.205 42.455,52.166 42.455,52.624 42.876,53.045 44.255,53.045 44.741,52.559 44.941,52.559 U28.L15@44.95,52.55 ; v1(31.72,27.825) R115.1@32.295,27.825
NetR116_1: R116.1 U28.L1 | length 44.1
  Top Layer w0.13: v1(39.345,24.175) 39.345,24.773 39.345,24.838 39.238,24.945 38.534,24.945 38.426,25.053 38.426,25.268 38.534,25.375 39.238,25.375 39.345,25.483 39.345,25.698 39.238,25.805 38.534,25.805 38.426,25.913 38.426,26.128 38.534,26.235 39.238,26.235 39.345,26.343 39.345,26.895 40.475,28.025 42.15,28.025 45.385,31.26 50.238,31.26 50.653,31.675 51.45,31.675 v1(51.95,32.175)
  Bottom Layer w0.13: v1(39.345,24.175) R116.1@39.345,24.75 ; v1(51.95,32.175) 51.95,35.025 55.275,38.35 55.275,41.625 55.275,52.375 55.1,52.55 U28.L1@54.05,52.55
NetR117_1: R117.1 U28.B9 | length 43.4
  Top Layer w0.1: v2(43.125,58.5) 43.35,58.725 v2(48.525,58.725)
  Signal Layer 2 w0.1: v1(37.045,24.175) 37.045,25.32 42.275,30.55 42.275,41.9 42.55,42.175 42.55,44.325 43.025,44.8 43.025,58.319 43.125,58.419 v2(43.125,58.5)
  Bottom Layer w0.13: v1(37.045,24.175) R117.1@37.045,24.75 ; v2(48.525,58.725) U28.B9@48.85,58.4
NetR118_2: R118.2 U28.N6 | length 44.6
  Top Layer w0.12: v1(35.92,24.175) 36.42,23.675 40.345,23.675 40.675,24.005 40.675,26.929 41.386,27.64 42.295,27.64 45.54,30.885 51.46,30.885 52.725,32.15 v1(53.75,32.15)
  Signal Layer 2 w0.12: v2(51.125,50.925) 51.125,48.75 50.725,48.35 50.725,45.1 50.6,44.975 50.6,36.075 53.75,32.925 v1(53.75,32.15)
  Bottom Layer w0.13: v1(35.92,24.175) R118.2@35.92,24.75 ; U28.N6@50.8,51.25 v2(51.125,50.925)
NetR119_1: R119.1 U28.K14 | length 47.1
  Top Layer w0.13: v1(32.75,25.175) 37.195,25.175 v1(38.195,24.175)
  Bottom Layer w0.13: v1(32.75,25.175) 32.403,25.175 29.915,27.663 29.915,36.515 34.585,41.185 34.585,49.385 36.036,50.836 36.4,50.836 38.086,50.836 38.685,51.435 41.399,51.435 42.225,52.261 42.225,52.45 42.225,52.719 42.781,53.275 44.35,53.275 44.725,52.9 44.95,52.9 45.3,52.9 U28.K14@45.6,53.2 ; v1(38.195,24.175) R119.1@38.195,24.75
NetR120_1: R120.1 U28.P3 | length 42.2
  Top Layer w0.13: v1(34.695,24.175) 35.57,23.3 40.5,23.3 41.05,23.85 41.05,26.773 41.542,27.265 42.465,27.265 45.626,30.426 45.628,30.425 v1(49.475,30.425)
  Bottom Layer w0.13: v1(34.695,24.175) R120.1@34.695,24.75 ; v1(49.475,30.425) 49.475,35.275 52.48,38.28 52.48,41.782 52.625,41.927 52.63,41.927 52.63,47.94 53.075,48.385 53.075,50.125 52.771,50.429 52.771,50.579 U28.P3@52.75,50.6
NetR122_2: R122.2 R123.1 U30.11 | length 3.1
  Bottom Layer w0.12: R123.1@35.35,13.675 R122.2@36.4,13.675 36.575,13.85 U30.11@36.575,15.7
NetSB11_2: SB11.2 U28.D7 | length 6.1
  Signal Layer 3 w0.3: v2(49.7,61.7) 49.7,58.2 v2(50.475,57.425)
  Bottom Layer w0.12: SB11.2@49.425,62.625 49.7,62.35 v2(49.7,61.7)
  Bottom Layer w0.13: U28.D7@50.15,57.1 v2(50.475,57.425)
NetSB20_2: SB20.2 U29.A4 | length 3.4
  Bottom Layer w0.13: U29.A4@36.32,32.65 SB20.2@36.32,36
NetSB22_1: SB22.1 U29.A5 | length 2.4
  Bottom Layer w0.13: SB22.1@32.945,32.65 U29.A5@35.32,32.65
NetTP3_1: TP3.1 U6.3 | length 4.6
  Top Layer w0.12: U6.3@7.175,65.65 8.275,65.65 v1(9.425,64.5)
  Bottom Layer w0.12: v1(9.425,64.5) TP3.1@11.3,64.5
NetTP5_1: TP5.1 U29.C5 | length 7.6
  Top Layer w0.12: v1(29.275,29.705) 30.225,30.655 30.23,30.65 v1(34.325,30.65)
  Bottom Layer w0.12: TP5.1@28.725,30.625 29.275,30.075 v1(29.275,29.705) v1@29.275,29.7 ; v1(34.325,30.65) U29.C5@35.32,30.65
NJTRST: R5.2 U28.C7 | length 44.5
  Top Layer w0.13: R5.2@38.55,89.125 38.73,89.125 38.985,89.38 38.985,89.41 39.25,89.675 49.375,89.675 v1(50.825,88.225)
  Signal Layer 2 w0.13: v2(50.475,58.075) 50.475,68.625 50.2,68.9 50.2,72.3 50.525,72.625 50.525,82.65 51.325,83.45 51.325,84.025 51.325,87.725 v1(50.825,88.225)
  Bottom Layer w0.13: U28.C7@50.15,57.75 v2(50.475,58.075)
NRST: B2.3 B2.4 C109.2 CN12.12 CN14.6 R4.2 R68.2 SB20.1 U4.5 U11.15 U14.1 U28.K3 | length 197.5
  Top Layer w0.1: v2(56.1,50.075) 56.1,48.55 58.125,46.525 62.125,46.525
  Top Layer w0.12: v1(22.75,94) 22.75,93.325 22.725,93.3 23,93.3 23.14,93.44 23.14,93.465 23.575,93.9 v1(23.575,94.925) ; v1(30.825,92.25) 31.925,91.15 33.829,91.15 34.316,90.663 35.854,89.125 R4.2@37.1,89.125 37.28,89.125 37.54,89.385 37.54,89.39 38.195,90.045 49.705,90.045 50.825,88.925 v1(58.75,88.925) ; v1(56.1,33.775) 57.35,33.775 58.025,34.45 U11.15@59.675,34.45 ; 62.125,46.525 64.475,46.525 66.6,48.65 v1(66.6,49.825) ; v1(67.275,26.4) 68.537,26.4 68.562,26.425 U14.1@68.575,26.412 69.137,26.412 69.75,27.025 69.75,29.2 70.06,29.51 70.06,30.56 B2.3@70.5,31 B2.4@70.5,22.1
  Signal Layer 2 w0.12: v2(53.075,52.875) 53.763,52.875 54.2,52.438 54.2,50.325 54.45,50.075 v2(56.1,50.075) ; v1(58.75,88.925) 58.75,82.95 59.225,82.475 59.225,70.225 59.475,69.975 59.475,68.85 61.825,66.5 61.825,55.8 v2(56.1,50.075) ; v1(67.275,26.4) 67.269,26.394 64.181,26.394 61.425,29.15 58.725,29.15 58.1,29.775 58.1,31.2 56.1,33.2 v1(56.1,33.775) v2(56.1,50.075)
  Bottom Layer w0.12: CN12.12@17.59,92.886 17.9,92.576 17.9,91.525 18.25,91.175 19.375,91.175 22.2,94 v1(22.75,94) ; R68.2@23.55,94 23.575,94.025 v1(23.575,94.925) 24.964,94.925 25.894,93.995 26.441,93.995 28.186,92.25 v1(30.825,92.25) ; SB20.1@36.32,37.1 36.32,38.195 36.325,38.19 36.325,38.125 39.525,38.125 47.775,29.875 50.45,29.875 54.35,33.775 v1(56.1,33.775) ; v1(66.6,49.825) 72.277,49.825 CN14.6@72.727,50.275
  Bottom Layer w0.13: U28.K3@52.75,53.2 v2(53.075,52.875)
  Bottom Layer w0.25: v2(56.1,50.075) 56.625,50.075 C109.2@56.65,50.1
OCS_25M: R38.2 R94.1 | length 28.4
  Top Layer w0.12: v1(58.225,44.55) 58.75,45.075 62.125,45.075 66.7,45.075 v1(68.05,43.725) ; R38.2@66.275,34.95 v1@68.2,34.95 ; v1(68.05,34.95) v1@68.2,34.95
  Signal Layer 2 w0.12: v1(68.05,34.95) v1(68.05,43.725)
  Bottom Layer w0.12: R94.1@57.65,51.225 57.65,51.13 57.845,50.935 57.94,50.935 58.225,50.65 v1(58.225,44.55)
OCSPI1_CLK: R105.1 U29.B2 | length 36.5
  Top Layer w0.13: v1(42.7,33.075) 43.572,33.075 43.638,33.075 43.745,33.182 43.745,33.919 43.853,34.027 44.068,34.027 44.175,33.919 44.175,33.169 44.283,33.062 44.498,33.062 44.605,33.169 44.605,33.919 44.713,34.027 44.928,34.027 45.035,33.919 45.035,33.169 45.143,33.062 45.358,33.062 45.465,33.169 45.465,33.919 45.573,34.027 45.788,34.027 45.895,33.919 45.895,33.169 46.003,33.062 46.218,33.062 46.325,33.169 46.325,33.919 46.433,34.027 46.648,34.027 46.755,33.919 46.755,33.169 46.863,33.062 47.078,33.062 47.185,33.169 47.185,33.919 47.293,34.027 47.508,34.027 47.615,33.919 47.615,33.169 47.723,33.062 47.938,33.062 48.045,33.169 48.045,33.919 48.152,34.027 48.368,34.027 48.475,33.919 48.475,33.182 48.582,33.075 49.123,33.075 v1(51.425,33.075)
  Bottom Layer w0.13: U29.B2@38.32,31.65 39.745,33.075 v1(42.7,33.075) ; v1(51.425,33.075) 51.425,35.037 54,37.612 54,44.525 R105.1@54.15,44.675
OCSPI1_DQS: R107.1 U29.C3 | length 4.3
  Bottom Layer w0.13: R107.1@33.22,31.1 33.27,31.15 36.82,31.15 U29.C3@37.32,30.65
OCSPI1_IO0: R118.1 U29.D3 | length 5
  Bottom Layer w0.13: R118.1@35.92,25.65 35.92,26.395 37.85,28.325 37.85,29.12 U29.D3@37.32,29.65
OCSPI1_IO1: R119.2 U29.D2 | length 4.4
  Bottom Layer w0.13: R119.2@38.195,25.65 38.375,25.83 38.375,27.025 38.775,27.425 38.775,29.195 U29.D2@38.32,29.65
OCSPI1_IO2: R109.2 U29.C4 | length 3.4
  Bottom Layer w0.13: R109.2@33.195,30.025 33.295,30.125 35.795,30.125 U29.C4@36.32,30.65
OCSPI1_IO3: R115.2 U29.D4 | length 3.9
  Bottom Layer w0.13: R115.2@33.195,27.825 33.675,27.825 35,29.15 35.82,29.15 U29.D4@36.32,29.65
OCSPI1_IO4: R114.2 U29.D5 | length 2.4
  Bottom Layer w0.13: R114.2@33.195,28.95 33.925,28.95 34.625,29.65 U29.D5@35.32,29.65
OCSPI1_IO5: R120.2 U29.E3 | length 4.1
  Bottom Layer w0.13: R120.2@34.695,25.65 34.695,26.025 U29.E3@37.32,28.65
OCSPI1_IO6: R117.2 U29.E2 | length 3.5
  Bottom Layer w0.13: R117.2@37.045,25.65 37.045,26.595 38.32,27.87 U29.E2@38.32,28.65
OCSPI1_IO7: R116.2 U29.E1 | length 3
  Bottom Layer w0.13: U29.E1@39.32,28.65 39.32,25.675 R116.2@39.345,25.65
OCSPI1_NCS: R106.2 R108.2 U29.C2 | length 37.8
  Top Layer w0.13: v1(29.475,33.55) 38.15,33.55 39.755,31.945 v1(41.22,31.945)
  Bottom Layer w0.13: v1(29.475,33.55) 29.475,36.625 34.205,41.355 34.205,49.542 35.879,51.216 35.935,51.216 36.125,51.406 R106.2@36.125,51.475 ; U29.C2@38.32,30.65 38.82,31.15 39.7,31.15 40.495,31.945 v1(41.22,31.945) R108.2@41.22,30.75
PC14: R88.2 U28.D2 | length 4.1
  Bottom Layer w0.12: U28.D2@53.4,57.1 53.647,57.1 53.947,57.4 55.075,57.4 55.425,57.75 R88.2@57.275,57.75
PC15: R89.2 U28.D1 | length 3.4
  Bottom Layer w0.12: U28.D1@54.05,57.1 56.4,57.1 56.85,56.65 R89.2@57.275,56.65
PDM_SAI1_CK: U20.4 U23.1 | length 17.6
  Signal Layer 2 w0.12: v1(70.9,75.8) 70.9,82.425 72.6,84.125 v1(72.6,88.8)
  Bottom Layer w0.12: U23.1@69.991,87.594 70.066,87.594 71.273,88.8 v1(72.6,88.8) ; v1(70.9,75.8) 70.9,76.559 U20.4@70.903,76.562
PDM_SAI1_CK1: U23.16 U28.L14 | length 65.4
  Top Layer w0.12: v1(44.325,69.225) 44.93,69.83 48.495,69.83 48.71,69.615 52.896,69.615 52.968,69.543 52.968,69.307 v1(53.05,69.225) ; v1(56.75,88.1) 56.832,88.182 57.174,88.182 57.316,88.325 59.95,88.325 60.55,87.725 66.975,87.725 69.415,90.165 69.79,90.165 v1(69.8,90.175)
  Signal Layer 2 w0.12: v1(53.05,69.225) 53.05,72.475 54.7,74.125 54.7,83.575 56.737,85.612 56.737,88.087 v1(56.75,88.1)
  Signal Layer 2 w0.13: v1(43.675,52.525) 43.675,52.561 43.965,52.851 43.965,55.957 43.875,56.047 43.875,66.45 44.325,66.9 v1(44.325,69.225)
  Bottom Layer w0.12: v1(69.8,90.175) 69.816,90.159 U23.16@69.816,88.169
  Bottom Layer w0.13: v1(43.675,52.525) 43.975,52.225 45.275,52.225 U28.L14@45.6,52.55
PDM_SAI1_CK1_EXT: CN2.4 U23.15 | length 12.8
  Signal Layer 2 w0.12: v1(69.125,82.45) v1(69.125,89.225)
  Bottom Layer w0.12: v1(69.125,82.45) 69.13,82.455 CN2.4@73.965,82.455 ; v1(69.125,89.225) 69.416,88.934 U23.15@69.416,88.169
PDM_SAI1_SD: U20.1 U23.6 | length 9.1
  Bottom Layer w0.12: U23.6@69.416,85.819 69.416,85.001 68.375,83.96 68.375,79.35 69.487,78.238 U20.1@70.081,78.238
PDM_SAI1_SD1: U23.5 U28.B10 | length 64.1
  Top Layer w0.12: v1(47.475,81.1) 50.575,81.1 54.225,84.75 59.2,84.75 59.26,84.75 59.365,84.855 59.365,85.1 59.47,85.205 59.68,85.205 59.785,85.1 59.785,83.79 59.89,83.685 60.1,83.685 60.205,83.79 60.205,85.1 60.31,85.205 60.52,85.205 60.625,85.1 60.625,83.79 60.73,83.685 60.94,83.685 61.045,83.79 61.045,85.1 61.15,85.205 61.36,85.205 61.465,85.1 61.465,83.79 61.57,83.685 61.78,83.685 61.885,83.79 61.885,85.1 61.99,85.205 62.2,85.205 62.305,85.1 62.305,83.79 62.41,83.685 62.62,83.685 62.725,83.79 62.725,85.1 62.83,85.205 63.04,85.205 63.145,85.1 63.145,83.79 63.25,83.685 63.46,83.685 63.565,83.79 63.565,84.645 63.67,84.75 63.9,84.75 v1(69.825,84.75)
  Signal Layer 2 w0.1: 47.7,65.625 47.7,58.9 v2(48.525,58.075)
  Signal Layer 2 w0.12: v1(47.475,81.1) 47.475,71.375 49.375,69.475 49.375,67.45 47.7,65.775 47.7,65.625
  Bottom Layer w0.12: U23.5@69.816,85.819 69.816,84.759 v1(69.825,84.75)
  Bottom Layer w0.13: U28.B10@48.2,58.4 v2(48.525,58.075)
PDM_SAI1_SD1_EXT: CN2.6 U23.4 | length 5.1
  Bottom Layer w0.12: U23.4@69.991,86.394 70.281,86.394 72.95,83.725 CN2.6@73.965,83.725
PDM_SAI1_SD2: CN2.5 U28.C3 | length 65.8
  Top Layer w0.09: 73.38,83.09 74.6,83.09 CN2.5@75.235,83.725
  Top Layer w0.1: v2(53.075,58.075) 53.425,58.425 55.117,58.425 56.842,56.7 57.726,56.7 61.45,52.976 61.45,51.875 62.74,50.585 66.16,50.585 v1(66.525,50.95)
  Top Layer w0.12: v1(66.375,83.725) 67.01,83.09 70.673,83.09 70.733,83.09 70.838,83.195 70.838,83.316 70.943,83.421 71.153,83.421 71.258,83.316 71.258,82.627 71.363,82.522 71.573,82.522 71.678,82.627 71.678,83.316 71.783,83.421 71.993,83.421 72.098,83.316 72.098,82.627 72.203,82.522 72.413,82.522 72.518,82.627 72.518,82.985 72.623,83.09 72.9,83.09 73.38,83.09
  Signal Layer 2 w0.12: v1(66.375,83.725) 63.625,80.975 63.625,75.525 64.85,74.3 64.85,68.325 64.57,68.045 64.57,64.877 64.578,64.869 64.585,64.788 64.585,64.54 64.62,64.505 66,63.125 66,55.775 66.525,55.25 v1(66.525,50.95)
  Bottom Layer w0.13: U28.C3@52.75,57.75 v2(53.075,58.075)
PDM_SAI1_SD3: CN2.7 U28.N3 | length 66.1
  Top Layer w0.09: 73.38,84.36 74.6,84.36 CN2.7@75.235,84.995
  Top Layer w0.1: v2(54.05,48.95) 54.55,48.95 57.575,45.925 65.5,45.925 v1(66.85,47.275)
  Top Layer w0.12: v1(67.725,84.15) 72.75,84.15 72.96,84.36 73.38,84.36
  Signal Layer 2 w0.12: v1(66.85,47.275) 66.85,47.335 67.075,47.56 67.075,55.325 66.35,56.05 66.35,63.2 64.81,64.74 64.79,64.968 64.79,67.657 64.791,67.918 65.225,68.353 65.225,74.45 63.845,75.83 63.845,80.884 66.061,83.1 66.675,83.1 v1(67.725,84.15)
  Bottom Layer w0.1: U28.N3@52.75,51.25 52.767,51.233 52.767,51.008 53.1,50.675 53.1,50.45 53.275,50.275 53.575,50.275 53.75,50.1 53.75,49.25 v2(54.05,48.95)
PMOD1: CN3.1 CN6.1 SB8.2 SB9.2 | length 66.2
  Top Layer w0.12: v1(5.15,68.7) 7.05,68.7 CN3.1@9.65,71.3
  Signal Layer 2 w0.12: v1(5.15,68.7) 6.25,67.6 6.25,66.25 6.525,65.975 6.525,51.575 6.25,51.3 6.25,21.325 7.05,20.525 11.285,20.525 CN6.1@12.59,19.22
  Bottom Layer w0.12: CN3.1@9.65,71.3 10.175,70.775 SB8.2@13.375,70.775 SB9.2@13.375,69.35
PMOD2: CN3.2 CN6.2 SB6.2 SB7.2 | length 62.4
  Signal Layer 2 w0.12: CN3.2@9.65,73.3 10.95,72 10.95,70.425 7.475,66.95 7.475,24.425 8.875,23.025 11.325,23.025 CN6.2@12.59,21.76
  Bottom Layer w0.12: CN3.2@9.65,73.3 13.05,73.3 SB6.2@13.375,73.625 SB7.2@13.375,72.2
PMOD3: CN3.3 CN6.3 SB4.2 SB5.2 | length 61.4
  Signal Layer 2 w0.12: CN3.3@9.65,75.3 11.17,73.78 11.17,70.32 8.15,67.3 8.15,26.25 8.825,25.575 11.315,25.575 CN6.3@12.59,24.3
  Bottom Layer w0.12: CN3.3@9.65,75.3 13.125,75.3 SB5.2@13.375,75.05 SB4.2@13.375,76.475
PMOD4: CN3.4 CN6.4 SB2.2 SB3.2 | length 60.5
  Signal Layer 2 w0.12: CN3.4@9.65,77.3 11.39,75.56 11.39,70.229 8.725,67.564 8.725,28.6 9.25,28.075 11.355,28.075 CN6.4@12.59,26.84
  Bottom Layer w0.12: CN3.4@9.65,77.3 11.125,77.3 11.725,77.9 SB3.2@13.375,77.9 SB2.2@13.375,79.325
PMOD11: CN3.11 CN6.7 U28.M12 | length 101
  Top Layer w0.12: v1(4.425,69.175) 5.525,69.175 CN3.11@7.65,71.3
  Top Layer w0.13: v1(5.675,50.8) 6.09,51.215 28.185,51.215 29.125,50.275 45.275,50.275 v2(46.575,51.575)
  Signal Layer 2 w0.12: v1(4.425,69.175) 4.425,68.65 5.675,67.4 5.675,66.05 5.4,65.775 5.4,51.575 5.675,51.3 v1(5.675,50.8) 5.675,20.35 6.805,19.22 CN6.7@10.05,19.22
  Bottom Layer w0.13: v2(46.575,51.575) U28.M12@46.9,51.9
PMOD12: CN3.12 CN6.8 U28.P13 | length 104.6
  Top Layer w0.12: v1(6.875,48.125) 11.45,48.125 13.175,46.4 32.5,46.4 35.325,43.575 42.275,43.575 42.775,43.075 46.075,43.075 v1(46.925,43.925)
  Signal Layer 2 w0.12: CN3.12@7.65,73.3 6.375,72.025 6.375,70.1 6.875,69.6 v1(6.875,48.125) 6.875,22.35 7.465,21.76 CN6.8@10.05,21.76
  Bottom Layer w0.12: U28.P13@46.25,50.6 46.575,50.275 46.575,44.275 v1(46.925,43.925)
RD_N: CN8.8 R111.1 U11.22 U12.6 | length 25.3
  Top Layer w0.13: v1(55.82,22.56) CN8.8@55.82,25.22 ; U11.22@61.875,32.25 61.935,32.19 61.935,31.388 62.279,31.044 62.279,30.679 v1(62.25,30.65) R111.1@62.25,30
  Bottom Layer w0.13: v1(55.82,22.56) 56.14,22.88 56.14,24.377 56.693,24.93 57.932,24.93 58.649,24.214 58.649,22.226 59.438,21.438 61.238,21.438 62.125,22.325 62.125,23.337 61.61,23.852 61.61,26.055 62.075,26.52 U12.6@62.075,26.82 62.221,26.966 62.221,27.731 62.585,28.094 62.585,30.315 v1(62.25,30.65)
